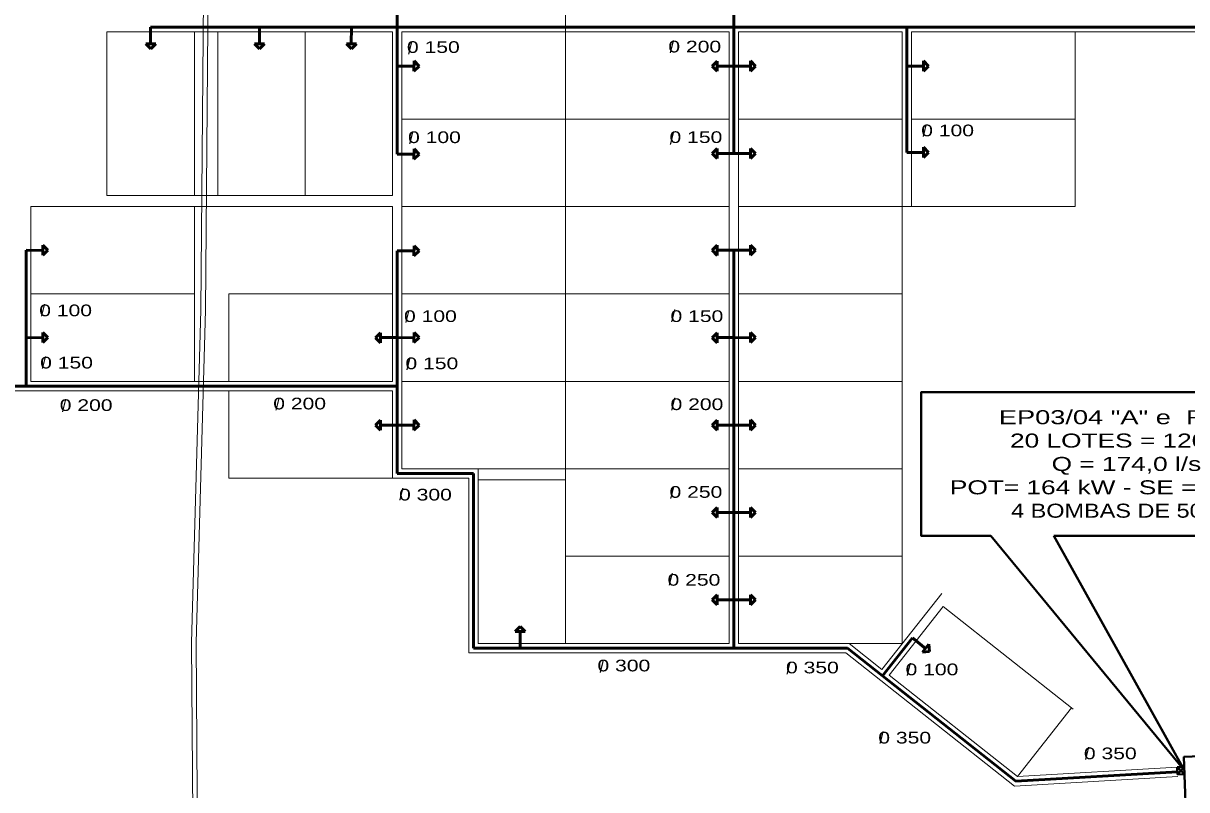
# Model space of a CAD drawing. Extents: x 312964 to 351929, y 9004151 to 9034973.
# Drawn here: x 343555 to 346044, y 9030073 to 9031712 of the extents above; entities that cross this region are included whole.
import ezdxf
from ezdxf.enums import TextEntityAlignment as Align

# ---------------------------------------------------------------- set-up
doc = ezdxf.new("R2010")
doc.units = 0
doc.header["$LTSCALE"] = 10
for name, color, linetype, lineweight in [('1', 7, 'Continuous', 13), ('2', 7, 'Continuous', 53), ('6', 7, 'Continuous', 13)]:
    doc.layers.add(name, color=color, linetype=linetype, lineweight=lineweight)

msp = doc.modelspace()

# ---------------------------------------------------------------- linework, layer by layer
at = {"layer": '1'}
for p, q in [((344715.24, 9032275.36), (344715.24, 9030385.36)), ((343734.24, 9031694.36), (344345.24, 9031694.36)), ((343734.24, 9031694.36), (343734.24, 9031344.36)), ((343921.24, 9031694.36), (343921.24, 9031344.36)), ((343971.24, 9031694.36), (343971.24, 9031344.36)), ((344158.24, 9031694.36), (344158.24, 9031344.36)), ((344345.24, 9031694.36), (344345.24, 9031344.36)), ((344365.24, 9031694.36), (345065.24, 9031694.36)), ((344365.24, 9031694.36), (344365.24, 9031320.36)), ((345065.24, 9031694.36), (345065.24, 9031320.36)), ((345085.24, 9031694.36), (345435.24, 9031694.36)), ((345085.24, 9031694.36), (345085.24, 9031320.36)), ((345435.24, 9031694.36), (345435.24, 9031320.36)), ((345455.24, 9031694.36), (346466.51, 9031694.36)), ((345455.24, 9031694.36), (345455.24, 9031320.36)), ((345805.24, 9031694.36), (345805.24, 9031320.36)), ((344365.24, 9031507.36), (345065.24, 9031507.36)), ((345085.24, 9031507.36), (345435.24, 9031507.36)), ((345455.24, 9031507.36), (345805.24, 9031507.36)), ((343971.24, 9031344.36), (343734.24, 9031344.36)), ((343971.24, 9031344.36), (344345.24, 9031344.36)), ((343971.24, 9031320.36), (343571.24, 9031320.36)), ((343571.24, 9031320.36), (343571.24, 9030946.36)), ((343921.24, 9031320.36), (343921.24, 9030946.36)), ((343971.24, 9031320.36), (344345.24, 9031320.36)), ((344345.24, 9031320.36), (344345.24, 9030946.36)), ((344365.24, 9031320.36), (345065.24, 9031320.36)), ((344365.24, 9031320.36), (345065.24, 9031320.36)), ((344365.24, 9031320.36), (344365.24, 9030759.36)), ((345065.24, 9031320.36), (345065.24, 9030385.36)), ((345085.24, 9031320.36), (345805.24, 9031320.36)), ((345085.24, 9031320.36), (345085.24, 9030385.36)), ((345085.24, 9031320.36), (345435.24, 9031320.36)), ((345435.24, 9031320.36), (345435.24, 9030385.36)), ((345455.24, 9031320.36), (345805.24, 9031320.36)), ((343921.24, 9031133.36), (343571.24, 9031133.36)), ((343995.24, 9031133.36), (344345.24, 9031133.36)), ((343995.24, 9031133.36), (343995.24, 9030946.36)), ((344365.24, 9031133.36), (345065.24, 9031133.36)), ((345085.24, 9031133.36), (345435.24, 9031133.36)), ((343995.24, 9030946.36), (343571.24, 9030946.36)), ((343995.24, 9030946.36), (344345.24, 9030946.36)), ((344365.24, 9030946.36), (345065.24, 9030946.36)), ((345085.24, 9030946.36), (345435.24, 9030946.36)), ((343995.24, 9030926.36), (344345.24, 9030926.36)), ((343995.24, 9030926.36), (343995.24, 9030739.36)), ((344345.24, 9030926.36), (344345.24, 9030739.36)), ((344365.24, 9030759.36), (345065.24, 9030759.36)), ((344528.24, 9030759.36), (344528.24, 9030385.36)), ((345085.24, 9030759.36), (345435.24, 9030759.36)), ((343995.24, 9030739.36), (344345.24, 9030739.36)), ((344345.24, 9030739.36), (344508.24, 9030739.36)), ((344508.24, 9030739.36), (344508.24, 9030365.36)), ((344528.24, 9030735.36), (344715.24, 9030735.36)), ((344715.24, 9030572.36), (345065.24, 9030572.36)), ((345085.24, 9030572.36), (345435.24, 9030572.36)), ((345391.72, 9030330.24), (345519.99, 9030492.71)), ((345407.42, 9030317.85), (345523.29, 9030464.62)), ((345523.29, 9030464.62), (345801.57, 9030244.93)), ((344528.24, 9030385.36), (345065.24, 9030385.36)), ((345085.24, 9030385.36), (345435.24, 9030385.36)), ((345321.91, 9030385.36), (345391.72, 9030330.24)), ((344508.24, 9030365.36), (345314.96, 9030365.36)), ((345314.96, 9030365.36), (345675.7, 9030080.57)), ((345407.42, 9030317.85), (345682.13, 9030100.97)), ((345682.13, 9030100.97), (345798, 9030247.75)), ((345682.13, 9030100.97), (346023.96, 9030120.61)), ((345675.7, 9030080.57), (346025.11, 9030100.65))]:
    msp.add_line(p, q, dxfattribs=at)
at = {"layer": '1', "lineweight": 40}
for p, q in [((346039.52, 9030106.2), (346023.96, 9030120.61)), ((346038.95, 9030121.19), (346024.54, 9030105.62))]:
    msp.add_line(p, q, dxfattribs=at)
at = {"layer": '1'}
msp.add_lwpolyline([(343995.24, 9030926.36), (343571.24, 9030926.36), (343364.24, 9030926.36)], dxfattribs=at)
at = {"layer": '1', "lineweight": 40}
for points in [[(346040.35, 9030084.55), (346038.12, 9030142.83), (346091.47, 9030144.88)], [(346093.71, 9030086.49), (346095.82, 9030028.2), (346042.47, 9030026.27), (346040.35, 9030084.55)]]:
    msp.add_lwpolyline(points, dxfattribs=at)
msp.add_lwpolyline([(346023.96, 9030120.61), (346024.54, 9030105.62), (346039.52, 9030106.2), (346038.95, 9030121.19)], close=True, dxfattribs=at)
at = {"layer": '2'}
for p, q in [((343827.62, 9031668.51), (343827.74, 9031704.36)), ((344060.56, 9031668.51), (344060.68, 9031704.36)), ((344256.94, 9031668.51), (344257.06, 9031704.36)), ((345445.24, 9031704.36), (345445.24, 9031436.25)), ((343817.1, 9031668.55), (343838.66, 9031668.47)), ((343827.84, 9031657.73), (343817.1, 9031668.55)), ((343827.84, 9031657.73), (343838.66, 9031668.47)), ((344050.04, 9031668.55), (344071.6, 9031668.47)), ((344060.79, 9031657.73), (344050.04, 9031668.55)), ((344060.79, 9031657.73), (344071.6, 9031668.47)), ((344246.42, 9031668.55), (344267.98, 9031668.47)), ((344257.16, 9031657.73), (344246.42, 9031668.55)), ((344257.16, 9031657.73), (344267.98, 9031668.47)), ((344391.05, 9031610.22), (344391.12, 9031631.78)), ((344401.87, 9031620.96), (344391.12, 9031631.78)), ((345028.61, 9031620.76), (345039.43, 9031631.5)), ((345039.43, 9031631.5), (345039.35, 9031609.94)), ((345111.05, 9031610.22), (345111.12, 9031631.78)), ((345121.87, 9031620.96), (345111.12, 9031631.78)), ((345481.05, 9031610.22), (345481.12, 9031631.78)), ((345491.87, 9031620.96), (345481.12, 9031631.78)), ((344391.09, 9031620.74), (344355.24, 9031620.86)), ((344401.87, 9031620.96), (344391.05, 9031610.22)), ((345028.61, 9031620.76), (345039.35, 9031609.94)), ((345039.39, 9031620.98), (345075.24, 9031620.86)), ((345111.09, 9031620.74), (345075.24, 9031620.86)), ((345121.87, 9031620.96), (345111.05, 9031610.22)), ((345481.09, 9031620.74), (345445.24, 9031620.86)), ((345491.87, 9031620.96), (345481.05, 9031610.22)), ((344391.09, 9031432.48), (344355.24, 9031432.6)), ((344391.05, 9031421.96), (344391.12, 9031443.52)), ((344401.87, 9031432.7), (344391.05, 9031421.96)), ((344401.87, 9031432.7), (344391.12, 9031443.52)), ((345028.61, 9031433.76), (345039.43, 9031444.5)), ((345028.61, 9031433.76), (345039.35, 9031422.94)), ((345039.43, 9031444.5), (345039.35, 9031422.94)), ((345039.39, 9031433.98), (345075.24, 9031433.86)), ((345111.09, 9031433.74), (345075.24, 9031433.86)), ((345111.05, 9031423.22), (345111.12, 9031444.78)), ((345121.87, 9031433.96), (345111.05, 9031423.22)), ((345121.87, 9031433.96), (345111.12, 9031444.78)), ((345481.09, 9031436.13), (345445.24, 9031436.25)), ((345481.05, 9031425.61), (345481.12, 9031447.17)), ((345491.87, 9031436.35), (345481.05, 9031425.61)), ((345491.87, 9031436.35), (345481.12, 9031447.17)), ((343597.05, 9031216.15), (343597.12, 9031237.71)), ((343607.87, 9031226.9), (343597.12, 9031237.71)), ((344391.05, 9031214.95), (344391.12, 9031236.5)), ((344401.87, 9031225.69), (344391.12, 9031236.5)), ((345028.61, 9031226.76), (345039.43, 9031237.5)), ((345039.43, 9031237.5), (345039.35, 9031215.94)), ((345111.05, 9031216.22), (345111.12, 9031237.78)), ((345121.87, 9031226.96), (345111.12, 9031237.78)), ((343561.24, 9031226.8), (343561.24, 9030936.36)), ((343597.09, 9031226.67), (343561.24, 9031226.8)), ((343607.87, 9031226.9), (343597.05, 9031216.15)), ((344355.24, 9031225.59), (344355.24, 9030749.36)), ((344391.09, 9031225.47), (344355.24, 9031225.59)), ((344401.87, 9031225.69), (344391.05, 9031214.95)), ((345028.61, 9031226.76), (345039.35, 9031215.94)), ((345039.39, 9031226.98), (345075.24, 9031226.86)), ((345075.24, 9031226.86), (345075.24, 9030375.36)), ((345111.09, 9031226.74), (345075.24, 9031226.86)), ((345121.87, 9031226.96), (345111.05, 9031216.22)), ((343597.09, 9031039.74), (343561.24, 9031039.86)), ((343597.05, 9031029.22), (343597.12, 9031050.78)), ((343607.87, 9031039.96), (343597.05, 9031029.22)), ((343607.87, 9031039.96), (343597.12, 9031050.78)), ((344308.61, 9031039.76), (344319.43, 9031050.5)), ((344308.61, 9031039.76), (344319.35, 9031028.94)), ((344319.43, 9031050.5), (344319.35, 9031028.94)), ((344319.39, 9031039.98), (344355.24, 9031039.86)), ((344391.09, 9031039.74), (344355.24, 9031039.86)), ((344391.05, 9031029.22), (344391.12, 9031050.78)), ((344401.87, 9031039.96), (344391.05, 9031029.22)), ((344401.87, 9031039.96), (344391.12, 9031050.78)), ((345028.61, 9031039.76), (345039.43, 9031050.5)), ((345028.61, 9031039.76), (345039.35, 9031028.94)), ((345039.43, 9031050.5), (345039.35, 9031028.94)), ((345039.39, 9031039.98), (345075.24, 9031039.86)), ((345111.09, 9031039.74), (345075.24, 9031039.86)), ((345111.05, 9031029.22), (345111.12, 9031050.78)), ((345121.87, 9031039.96), (345111.05, 9031029.22)), ((345121.87, 9031039.96), (345111.12, 9031050.78)), ((343457.74, 9030936.36), (344355.24, 9030936.36)), ((344308.61, 9030852.76), (344319.43, 9030863.5)), ((344319.43, 9030863.5), (344319.35, 9030841.94)), ((344391.05, 9030842.22), (344391.12, 9030863.78)), ((344401.87, 9030852.96), (344391.12, 9030863.78)), ((345028.61, 9030852.76), (345039.43, 9030863.5)), ((345039.43, 9030863.5), (345039.35, 9030841.94)), ((345111.05, 9030842.22), (345111.12, 9030863.78)), ((345121.87, 9030852.96), (345111.12, 9030863.78)), ((344308.61, 9030852.76), (344319.35, 9030841.94)), ((344319.39, 9030852.98), (344355.24, 9030852.86)), ((344391.09, 9030852.74), (344355.24, 9030852.86)), ((344401.87, 9030852.96), (344391.05, 9030842.22)), ((345028.61, 9030852.76), (345039.35, 9030841.94)), ((345039.39, 9030852.98), (345075.24, 9030852.86)), ((345111.09, 9030852.74), (345075.24, 9030852.86)), ((345121.87, 9030852.96), (345111.05, 9030842.22)), ((344355.24, 9030749.36), (344518.24, 9030749.36)), ((344518.24, 9030749.36), (344518.24, 9030375.36)), ((345028.61, 9030665.76), (345039.43, 9030676.5)), ((345028.61, 9030665.76), (345039.35, 9030654.94)), ((345039.43, 9030676.5), (345039.35, 9030654.94)), ((345039.39, 9030665.98), (345075.24, 9030665.86)), ((345111.09, 9030665.74), (345075.24, 9030665.86)), ((345111.05, 9030655.22), (345111.12, 9030676.78)), ((345121.87, 9030665.96), (345111.05, 9030655.22)), ((345121.87, 9030665.96), (345111.12, 9030676.78)), ((345028.61, 9030478.76), (345039.43, 9030489.5)), ((345039.43, 9030489.5), (345039.35, 9030467.94)), ((345111.05, 9030468.22), (345111.12, 9030489.78)), ((345121.87, 9030478.96), (345111.12, 9030489.78)), ((345028.61, 9030478.76), (345039.35, 9030467.94)), ((345039.39, 9030478.98), (345075.24, 9030478.86)), ((345111.09, 9030478.74), (345075.24, 9030478.86)), ((345121.87, 9030478.96), (345111.05, 9030468.22)), ((344618.34, 9030421.99), (344607.53, 9030411.25)), ((344629.09, 9030411.17), (344607.53, 9030411.25)), ((344618.34, 9030421.99), (344629.09, 9030411.17)), ((344618.57, 9030411.21), (344618.45, 9030375.36)), ((345485.57, 9030375.12), (345457.51, 9030397.43)), ((344518.24, 9030375.36), (345318.43, 9030375.36)), ((345479.02, 9030366.89), (345492.44, 9030383.76)), ((345494.17, 9030368.62), (345479.02, 9030366.89)), ((345494.17, 9030368.62), (345492.44, 9030383.76)), ((345393.38, 9030316.2), (345678.91, 9030090.77)), ((345678.91, 9030090.77), (346024.53, 9030110.63))]:
    msp.add_line(p, q, dxfattribs=at)
for points in [[(344355.24, 9032180.2), (344355.24, 9031704.36), (344355.24, 9031432.6)], [(345075.24, 9032179.83), (345075.24, 9031704.36), (345075.24, 9031433.86)], [(343827.74, 9031704.36), (344345.24, 9031704.36), (345065.24, 9031704.36), (345435.24, 9031704.36), (346464.94, 9031704.36)], [(345318.43, 9030375.36), (345393.38, 9030316.2), (345457.51, 9030397.43)]]:
    msp.add_lwpolyline(points, dxfattribs=at)
at = {"layer": '2', "lineweight": 40}
for points in [[(345476, 9030832.6), (345476, 9030923.03), (345653.49, 9030923.03)], [(345653.49, 9030923.03), (346360.23, 9030923.03), (346360.23, 9030616.21), (345759.63, 9030616.21)], [(345624.98, 9030616.21), (345476, 9030616.21), (345476, 9030832.6)], [(345624.98, 9030616.21), (346039.24, 9030113.69), (345759.63, 9030616.21)]]:
    msp.add_lwpolyline(points, dxfattribs=at)
at = {"layer": '6'}
for p, q in [((343935.24, 9031098.44), (343945.24, 9032315.44)), ((343915.24, 9030387.64), (343935.24, 9031098.64)), ((343920.24, 9029625.29), (343915.24, 9030387.29))]:
    msp.add_line(p, q, dxfattribs=at)
msp.add_lwpolyline([(343925.24, 9028600.36), (343934.24, 9029095.36), (343930.24, 9029625.36), (343925.24, 9030387.36), (343945.24, 9031098.36), (343955.24, 9032315.36)], dxfattribs=at)

# ---------------------------------------------------------------- texts
at = {"layer": '2'}
for s, height, width, p in [('0 150', 25, 1.35, (344432.47, 9031649.06)), ('0 200', 25, 1.35, (344991.71, 9031650.12)), ('0 100', 25, 1.35, (344434.85, 9031456.17)), ('0 150', 25, 1.35, (344994.22, 9031456.37)), ('0 100', 25, 1.35, (345532.67, 9031470.67)), ('0 100', 25, 1.35, (343645.8, 9031085.68)), ('0 100', 25, 1.35, (344426.21, 9031073.37)), ('0 150', 25, 1.35, (344996.33, 9031073.37)), ('0 150', 25, 1.35, (343647.78, 9030973.85)), ('0 150', 25, 1.35, (344429.31, 9030972.37)), ('0 200', 25, 1.35, (343689.73, 9030883.01)), ('0 200', 25, 1.35, (344146.44, 9030886.38)), ('0 200', 25, 1.35, (344996.39, 9030884.95)), ('EP03/04 "A" e  RS06', 30, 1.45, (345915.17, 9030854.69)), ('20 LOTES = 120 ha', 30, 1.4, (345915.17, 9030804.69)), ('Q = 174,0 l/s', 30, 1.4, (345915.17, 9030754.69)), ('POT= 164 kW - SE = 225 kVA', 30, 1.4, (345915.17, 9030704.69)), ('0 300', 25, 1.35, (344415.65, 9030691.47)), ('0 250', 25, 1.35, (344994.22, 9030697.29)), ('4 BOMBAS DE 50 HP', 30, 1.25, (345915.17, 9030654.69)), ('0 250', 25, 1.35, (344989.99, 9030509.21)), ('0 300', 25, 1.35, (344840.08, 9030325.88)), ('0 350', 25, 1.35, (345243.39, 9030321.65)), ('0 100', 25, 1.35, (345499.18, 9030317.56)), ('0 350', 25, 1.35, (345440.83, 9030171.56)), ('0 350', 25, 1.35, (345880.7, 9030137.87))]:
    msp.add_text(s, height=height, dxfattribs=dict(at, width=width)).set_placement(p, align=Align.CENTER)
for p in [(344382.89, 9031646.55), (344942.74, 9031649.38), (344385.27, 9031454.71), (344942.94, 9031453.37), (345483.63, 9031469.92), (343597.45, 9031085.58), (344376.86, 9031072.03), (344945.69, 9031073.97), (343599.43, 9030973.75), (344379.2, 9030971.3), (343642.47, 9030881.3), (344099.18, 9030884.67), (344945.69, 9030884.83), (344364.04, 9030692.13), (344943.58, 9030695.69), (344940.5, 9030510.38), (344792.69, 9030323.36), (345192.48, 9030320.23), (345449.65, 9030317.29), (345391.3, 9030171.3), (345831.18, 9030137.6)]:
    msp.add_text('/', height=25, dxfattribs=at).set_placement(p, align=Align.CENTER)

doc.saveas('drawing.dxf')
